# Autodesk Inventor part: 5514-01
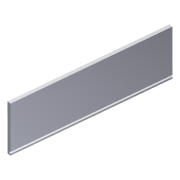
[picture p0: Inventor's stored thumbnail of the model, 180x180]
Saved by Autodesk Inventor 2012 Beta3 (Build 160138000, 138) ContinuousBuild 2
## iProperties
Created: 2011-02
Part Number: 5514-01
Material: Default
Document SubType Name: Modeling
Designer: Beta-8540w
Density: 1 g/cm^3
Author: Beta-8540w
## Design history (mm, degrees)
sketch "Sketch1"
  geometry: L1 (-273.05, -88.9)-(273.05, -88.9); L2 (273.05, -88.9)-(273.05, 88.9); L3 (273.05, 88.9)-(-273.05, 88.9); L4 (-273.05, 88.9)-(-273.05, -88.9); 3 further points
  constraints: 8 end point, 2 midpoint, 2 parallel, 1 horizontal, 1 horizontal alignment, 1 perpendicular, 1 vertical alignment
  dimensions: "width" = 546.1 distance of L3.end L2.end; "height" = 177.8 distance of L2.end L1.end
extrude "Extrusion1" new body sketch "Sketch1" distance "d2" = 12.7; taper "d3" = 0 deg
sketch "Sketch2"
  geometry: L1 (273.05, -88.9)-(-273.05, -88.9) reference; L2 (273.05, 88.9)-(273.05, -88.9) reference; L3 (-273.05, -88.9)-(-273.05, 88.9) reference; L4 (-273.05, -82.55)-(273.05, -82.55); L5 (273.05, -82.55)-(273.05, -76.2); L6 (273.05, -76.2)-(-273.05, -76.2); L7 (-273.05, -76.2)-(-273.05, -82.55); 1 further point
  constraints: 8 end point, 2 parallel, 2 point on line, 1 horizontal, 1 perpendicular
  dimensions: "d4" = 6.35 distance between parallel lines of L1 L4; "thickness" = 6.35 distance of L6.end L4.start
extrude "Extrusion2" cut sketch "Sketch2" distance "d6" = 6.35; taper "d7" = 0 deg
body "Solid1"
